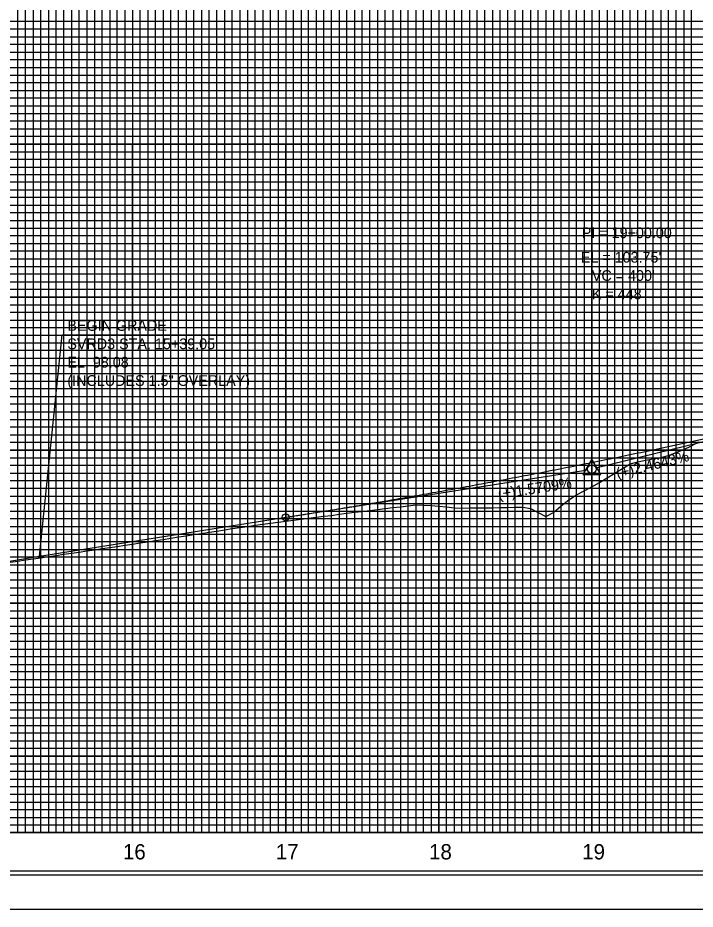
# Model space of a CAD drawing. Extents: x 2345490 to 2436403, y 465165 to 573888.
# Drawn here: x 2382292 to 2382734, y 500558 to 501140 of the extents above; entities that cross this region are included whole.
import ezdxf

# ---------------------------------------------------------------- set-up
doc = ezdxf.new("R2010")
doc.units = 0
for name, color, linetype in [('Exist Vertical Profile Horizontal Axis Label Major', 7, 'Continuous'), ('Old_Level_1', 7, 'Continuous'), ('Old_Level_18', 7, 'Continuous'), ('Old_Level_2', 7, 'Continuous'), ('Old_Level_41', 7, 'Continuous'), ('Old_Level_42', 7, 'Continuous'), ('Old_Level_43', 7, 'Continuous'), ('Old_Level_50', 7, 'Continuous'), ('Old_Level_51', 7, 'Continuous'), ('Old_Level_57', 7, 'Continuous'), ('Old_Level_63', 7, 'Continuous')]:
    doc.layers.add(name, color=color, linetype=linetype)

msp = doc.modelspace()

# ---------------------------------------------------------------- linework, layer by layer
at = {"layer": 'Old_Level_1'}
msp.add_lwpolyline([(2382286.7988, 500784.53371), (2382291.7988, 500785.26166), (2382296.7988, 500785.99237), (2382301.7988, 500786.72582), (2382306.7988, 500787.4614), (2382311.7988, 500788.18175), (2382316.7988, 500788.93271), (2382321.7988, 500789.68367), (2382326.7988, 500790.43463), (2382331.7988, 500791.18559), (2382336.7988, 500791.91779), (2382341.7988, 500792.64217), (2382346.7988, 500793.39156), (2382351.7988, 500794.14095), (2382356.7988, 500794.89034), (2382361.7988, 500795.63973), (2382366.7988, 500796.35105), (2382371.7988, 500797.12712), (2382376.7988, 500797.90319), (2382381.7988, 500798.67927), (2382386.7988, 500799.45534), (2382391.7988, 500800.23141), (2382396.7988, 500801.02584), (2382401.7988, 500801.8028), (2382406.7988, 500802.57976), (2382411.7988, 500803.35671), (2382416.7988, 500804.13367), (2382421.7988, 500804.91063), (2382426.7988, 500805.70098), (2382431.7988, 500806.44775), (2382436.7988, 500807.19218), (2382441.7988, 500807.9289), (2382446.7988, 500808.65766), (2382451.7988, 500809.36537), (2382456.7988, 500810.01704), (2382461.7988, 500810.71318), (2382466.7988, 500811.40027), (2382471.7988, 500812.07831), (2382476.7988, 500812.74727), (2382481.7988, 500813.35217), (2382486.7988, 500813.92844), (2382491.7988, 500814.54604), (2382496.7988, 500815.14977), (2382501.7988, 500815.87578), (2382506.7988, 500816.59153), (2382511.7988, 500817.18644), (2382516.7988, 500817.76146), (2382521.7988, 500818.3398), (2382526.7988, 500818.94403), (2382531.7988, 500819.55269), (2382536.7988, 500820.16259), (2382541.7988, 500820.76124), (2382546.7988, 500821.34863), (2382551.7988, 500821.92208), (2382556.7988, 500821.90141), (2382561.7988, 500821.52941), (2382566.7988, 500821.11082), (2382571.7988, 500820.64567), (2382576.7988, 500820.13395), (2382581.7988, 500819.90991), (2382586.7988, 500820.14813), (2382591.7988, 500820.14484), (2382596.7988, 500820.05054), (2382601.7988, 500820.01566), (2382606.7988, 500820.18657), (2382611.7988, 500820.31592), (2382616.7988, 500820.40371), (2382621.7988, 500820.44993), (2382626.7988, 500819.63463), (2382631.7988, 500817.08439), (2382636.7988, 500814.42424), (2382641.7988, 500817.00666), (2382646.7988, 500821.44876), (2382651.7988, 500825.21801), (2382656.7988, 500828.58451), (2382661.7988, 500831.10502), (2382666.7988, 500833.85905), (2382671.7988, 500836.69552), (2382676.7988, 500839.61461), (2382681.7988, 500842.61624), (2382686.7988, 500845.70031), (2382691.7988, 500848.86675), (2382696.7988, 500850.17491), (2382701.7988, 500851.12826), (2382706.7988, 500852.07957), (2382711.7988, 500853.0288), (2382716.7988, 500854.21109), (2382721.7988, 500856.22509), (2382726.7988, 500858.18432), (2382731.7988, 500860.50884), (2382736.7988, 500863.10854)], dxfattribs=at)
at = {"layer": 'Old_Level_18'}
msp.add_lwpolyline([(2383216.79875, 501632.775), (2381716.79875, 501632.775), (2381716.79875, 500582.775), (2383216.79875, 500582.775)], close=True, dxfattribs=at)
at = {"layer": 'Old_Level_2'}
for p, q in [((2382305.849, 500788.57525), (2382320.78925, 500933.0505)), ((2382320.78925, 500933.0505), (2382465.1055, 500933.0505)), ((2382866.799, 500894.56075), (2382669.46925, 500845.933)), ((2382466.799, 500813.858), (2382664.0825, 500844.84825)), ((2382305.849, 500788.57525), (2382466.799, 500813.858)), ((2382266.799, 500781.77575), (2382305.849, 500788.57525))]:
    msp.add_line(p, q, dxfattribs=at)
msp.add_lwpolyline([(2382660.99325, 500841.824), (2382672.73575, 500841.824), (2382666.86475, 500851.94975)], close=True, dxfattribs=at)
for centre, radius in [((2382666.799, 500845.275), 2.75), ((2382666.799, 500845.275), 2.75), ((2382466.799, 500813.858), 2.25)]:
    msp.add_circle(centre, radius, dxfattribs=at)
msp.add_spline([(2382466.799, 500813.858), (2382474.799, 500815.12175), (2382482.799, 500816.4), (2382490.799, 500817.6925), (2382498.799, 500818.99925), (2382506.799, 500820.32025), (2382514.799, 500821.6555), (2382522.799, 500823.005), (2382530.799, 500824.369), (2382538.799, 500825.74725), (2382546.799, 500827.1395), (2382554.799, 500828.5465), (2382562.799, 500829.9675), (2382570.799, 500831.40275), (2382578.799, 500832.8525), (2382586.799, 500834.3165), (2382594.799, 500835.79475), (2382602.799, 500837.28725), (2382610.799, 500838.794), (2382618.799, 500840.31525), (2382626.799, 500841.85075), (2382634.799, 500843.4005), (2382642.799, 500844.9645), (2382650.799, 500846.54275), (2382658.799, 500848.13525), (2382666.799, 500849.74225), (2382674.799, 500851.3635), (2382682.799, 500852.999), (2382690.799, 500854.64875), (2382698.799, 500856.31275), (2382706.799, 500857.99125), (2382714.799, 500859.684), (2382722.799, 500861.391), (2382730.799, 500863.11225), (2382738.799, 500864.84775), (2382746.799, 500866.5975), (2382754.799, 500868.36175), (2382762.799, 500870.14025), (2382770.799, 500871.933), (2382778.799, 500873.74), (2382786.799, 500875.56125), (2382794.799, 500877.397), (2382802.799, 500879.24675), (2382810.799, 500881.111), (2382818.799, 500882.9895), (2382826.799, 500884.8825), (2382834.799, 500886.7895), (2382842.799, 500888.711), (2382850.799, 500890.6465), (2382858.799, 500892.5965), (2382866.799, 500894.56075)], degree=3, dxfattribs=at)
at = {"layer": 'Old_Level_41'}
msp.add_line((2383216.79875, 500607.775), (2381716.79875, 500607.775), dxfattribs=at)
for points in [[(2382241.79875, 500607.775), (2382291.79875, 500607.775), (2382291.79875, 501632.775)], [(2382266.79875, 500607.775), (2382316.79875, 500607.775), (2382316.79875, 501632.775)], [(2382341.79875, 501632.775), (2382341.79875, 500607.775), (2382391.79875, 500607.775), (2382391.79875, 501632.775)], [(2382366.79875, 501632.775), (2382366.79875, 500607.775), (2382416.79875, 500607.775), (2382416.79875, 501632.775)], [(2382441.79875, 501632.775), (2382441.79875, 500607.775), (2382491.79875, 500607.775), (2382491.79875, 501632.775)], [(2382466.79875, 501632.775), (2382466.79875, 500607.775), (2382516.79875, 500607.775), (2382516.79875, 501632.775)], [(2382541.79875, 501632.775), (2382541.79875, 500607.775), (2382591.79875, 500607.775), (2382591.79875, 501632.775)], [(2382566.79875, 501632.775), (2382566.79875, 500607.775), (2382616.79875, 500607.775), (2382616.79875, 501632.775)], [(2382641.79875, 501632.775), (2382641.79875, 500607.775), (2382691.79875, 500607.775), (2382691.79875, 501632.775)], [(2382666.79875, 501632.775), (2382666.79875, 500607.775), (2382716.79875, 500607.775), (2382716.79875, 501632.775)], [(2383216.79875, 501132.775), (2381716.79875, 501132.775), (2381716.79875, 501082.775), (2383216.79875, 501082.775)], [(2383216.79875, 501032.775), (2381716.79875, 501032.775), (2381716.79875, 500982.775), (2383216.79875, 500982.775)], [(2383216.79875, 500957.775), (2381716.79875, 500957.775), (2381716.79875, 501007.775), (2383216.79875, 501007.775)], [(2383216.79875, 500932.775), (2381716.79875, 500932.775), (2381716.79875, 500882.775), (2383216.79875, 500882.775)], [(2383216.79875, 500857.775), (2381716.79875, 500857.775), (2381716.79875, 500907.775), (2383216.79875, 500907.775)], [(2383216.79875, 500832.775), (2381716.79875, 500832.775), (2381716.79875, 500782.775), (2383216.79875, 500782.775)], [(2383216.79875, 500732.775), (2381716.79875, 500732.775), (2381716.79875, 500682.775), (2383216.79875, 500682.775)], [(2383216.79875, 500657.775), (2381716.79875, 500657.775), (2381716.79875, 500707.775), (2383216.79875, 500707.775)], [(2383216.79875, 500632.775), (2381716.79875, 500632.775)]]:
    msp.add_lwpolyline(points, dxfattribs=at)
at = {"layer": 'Old_Level_42'}
for points in [[(2383216.79875, 501057.775), (2381716.79875, 501057.775), (2381716.79875, 501107.775), (2383216.79875, 501107.775)], [(2383216.79875, 500757.775), (2381716.79875, 500757.775), (2381716.79875, 500807.775), (2383216.79875, 500807.775)]]:
    msp.add_lwpolyline(points, dxfattribs=at)
at = {"layer": 'Old_Level_43'}
for points in [[(2382296.79875, 500607.775), (2382296.79875, 501632.775)], [(2382301.79875, 501632.775), (2382301.79875, 500607.775), (2382306.79875, 500607.775), (2382306.79875, 501632.775)], [(2382311.79875, 501632.775), (2382311.79875, 500607.775), (2382321.79875, 500607.775), (2382321.79875, 501632.775)], [(2382326.79875, 501632.775), (2382326.79875, 500607.775), (2382326.79875, 500607.775), (2382331.79875, 500607.775), (2382331.79875, 501632.775)], [(2382336.79875, 501632.775), (2382336.79875, 500607.775), (2382346.79875, 500607.775), (2382346.79875, 501632.775)], [(2382351.79875, 501632.775), (2382351.79875, 500607.775), (2382356.79875, 500607.775), (2382356.79875, 501632.775)], [(2382361.79875, 501632.775), (2382361.79875, 500607.775), (2382371.79875, 500607.775), (2382371.79875, 501632.775)], [(2382376.79875, 501632.775), (2382376.79875, 500607.775), (2382381.79875, 500607.775), (2382381.79875, 501632.775)], [(2382386.79875, 501632.775), (2382386.79875, 500607.775), (2382396.79875, 500607.775), (2382396.79875, 501632.775)], [(2382401.79875, 501632.775), (2382401.79875, 500607.775), (2382406.79875, 500607.775), (2382406.79875, 501632.775)], [(2382411.79875, 501632.775), (2382411.79875, 500607.775), (2382421.79875, 500607.775), (2382421.79875, 501632.775)], [(2382426.79875, 501632.775), (2382426.79875, 500607.775), (2382431.79875, 500607.775), (2382431.79875, 501632.775)], [(2382436.79875, 501632.775), (2382436.79875, 500607.775), (2382446.79875, 500607.775), (2382446.79875, 501632.775)], [(2382451.79875, 501632.775), (2382451.79875, 500607.775), (2382456.79875, 500607.775), (2382456.79875, 501632.775)], [(2382461.79875, 501632.775), (2382461.79875, 500607.775), (2382471.79875, 500607.775), (2382471.79875, 501632.775)], [(2382476.79875, 501632.775), (2382476.79875, 500607.775)], [(2382476.79875, 500607.775), (2382481.79875, 500607.775), (2382481.79875, 501632.175)], [(2382486.79875, 501632.175), (2382486.79875, 500607.775), (2382496.79875, 500607.775), (2382496.79875, 501632.775)], [(2382501.79875, 501632.775), (2382501.79875, 500607.775), (2382506.79875, 500607.775), (2382506.79875, 501632.775)], [(2382511.79875, 501632.775), (2382511.79875, 500607.775), (2382521.79875, 500607.775), (2382521.79875, 501632.775)], [(2382526.79875, 501632.775), (2382526.79875, 500607.775), (2382531.79875, 500607.775), (2382531.79875, 501632.775)], [(2382536.79875, 501632.775), (2382536.79875, 500607.775), (2382546.79875, 500607.775), (2382546.79875, 501632.775)], [(2382551.79875, 501632.775), (2382551.79875, 500607.775), (2382556.79875, 500607.775), (2382556.79875, 501632.775)], [(2382561.79875, 501632.775), (2382561.79875, 500607.775), (2382571.79875, 500607.775), (2382571.79875, 501632.775)], [(2382576.79875, 501632.775), (2382576.79875, 500607.775), (2382581.79875, 500607.775), (2382581.79875, 501632.775)], [(2382586.79875, 501632.775), (2382586.79875, 500607.775), (2382596.79875, 500607.775), (2382596.79875, 501632.775)], [(2382601.79875, 501632.775), (2382601.79875, 500607.775), (2382606.79875, 500607.775), (2382606.79875, 501632.775)], [(2382611.79875, 501632.775), (2382611.79875, 500607.775), (2382621.79875, 500607.775), (2382621.79875, 501632.775)], [(2382626.79875, 501632.775), (2382626.79875, 500607.775), (2382631.79875, 500607.775), (2382631.79875, 501632.775)], [(2382636.79875, 501632.775), (2382636.79875, 500607.775), (2382646.79875, 500607.775), (2382646.79875, 501632.775)], [(2382651.79875, 501632.775), (2382651.79875, 500607.775), (2382656.79875, 500607.775), (2382656.79875, 501632.775)], [(2382661.79875, 501632.775), (2382661.79875, 500607.775), (2382671.79875, 500607.775), (2382671.79875, 501632.775)], [(2382676.79875, 501632.775), (2382676.79875, 500607.775), (2382681.79875, 500607.775), (2382681.79875, 501632.775)], [(2382686.79875, 501632.775), (2382686.79875, 500607.775), (2382696.79875, 500607.775), (2382696.79875, 501632.775)], [(2382701.79875, 501632.775), (2382701.79875, 500607.775), (2382706.79875, 500607.775), (2382706.79875, 501632.775)], [(2382711.79875, 501632.775), (2382711.79875, 500607.775), (2382721.79875, 500607.775), (2382721.79875, 501632.775)], [(2382726.79875, 501632.775), (2382726.79875, 500607.775), (2382731.79875, 500607.775), (2382731.79875, 501632.775)], [(2383166.79875, 501137.775), (2381766.79875, 501137.775), (2381766.79875, 501127.775), (2383166.79875, 501127.775)], [(2383166.79875, 501122.775), (2381766.79875, 501122.775), (2381766.79875, 501117.775), (2383166.79875, 501117.775)], [(2383166.79875, 501112.775), (2381766.79875, 501112.775)], [(2381766.79875, 501102.775), (2383166.79875, 501102.775)], [(2383166.79875, 501097.775), (2381766.79875, 501097.775), (2381766.79875, 501092.775), (2383166.79875, 501092.775)], [(2383166.79875, 501087.775), (2381766.79875, 501087.775), (2381766.79875, 501077.775), (2383166.79875, 501077.775)], [(2383166.79875, 501072.775), (2381766.79875, 501072.775), (2381766.79875, 501067.775), (2383166.79875, 501067.775)], [(2383166.79875, 501062.775), (2381766.79875, 501062.775), (2381766.79875, 501052.775), (2383166.79875, 501052.775)], [(2383166.79875, 501047.775), (2381766.79875, 501047.775), (2381766.79875, 501042.775), (2383166.79875, 501042.775)], [(2383166.79875, 501037.775), (2381766.79875, 501037.775), (2381766.79875, 501027.775), (2383166.79875, 501027.775)], [(2383166.79875, 501022.775), (2381766.79875, 501022.775), (2381766.79875, 501017.775), (2383166.79875, 501017.775)], [(2383166.79875, 501012.775), (2381766.79875, 501012.775), (2381766.79875, 501002.775), (2383166.79875, 501002.775)], [(2383166.79875, 500997.775), (2381766.79875, 500997.775), (2381766.79875, 500992.775), (2383166.79875, 500992.775)], [(2383166.79875, 500987.775), (2381766.79875, 500987.775), (2381766.79875, 500977.775), (2383166.79875, 500977.775)], [(2383166.79875, 500972.775), (2381766.79875, 500972.775), (2381766.79875, 500967.775), (2383166.79875, 500967.775)], [(2383166.79875, 500962.775), (2381766.79875, 500962.775), (2381766.79875, 500952.775), (2383166.79875, 500952.775)], [(2383166.79875, 500947.775), (2381766.79875, 500947.775), (2381766.79875, 500942.775), (2383166.79875, 500942.775)], [(2383166.79875, 500937.775), (2381766.79875, 500937.775), (2381766.79875, 500927.775), (2383166.79875, 500927.775)], [(2383166.79875, 500922.775), (2381766.79875, 500922.775), (2381766.79875, 500917.775), (2383166.79875, 500917.775)], [(2383166.79875, 500912.775), (2381766.79875, 500912.775), (2381766.79875, 500902.775), (2383166.79875, 500902.775)], [(2383166.79875, 500897.775), (2381766.79875, 500897.775), (2381766.79875, 500892.775), (2383166.79875, 500892.775)], [(2383166.79875, 500887.775), (2381766.79875, 500887.775), (2381766.79875, 500877.775), (2383166.79875, 500877.775)], [(2383166.79875, 500872.775), (2381766.79875, 500872.775), (2381766.79875, 500867.775), (2383166.79875, 500867.775)], [(2383166.79875, 500862.775), (2381766.79875, 500862.775), (2381766.79875, 500852.775), (2383166.79875, 500852.775)], [(2383166.79875, 500847.775), (2381766.79875, 500847.775), (2381766.79875, 500842.775), (2383166.79875, 500842.775)], [(2383166.79875, 500837.775), (2381766.79875, 500837.775), (2381766.79875, 500827.775), (2383166.79875, 500827.775)], [(2383166.79875, 500822.775), (2381766.79875, 500822.775), (2381766.79875, 500817.775), (2383166.79875, 500817.775)], [(2383166.79875, 500812.775), (2381766.79875, 500812.775)], [(2381766.79875, 500802.775), (2383166.79875, 500802.775)], [(2383166.79875, 500797.775), (2381766.79875, 500797.775), (2381766.79875, 500792.775), (2383166.79875, 500792.775)], [(2383166.79875, 500787.775), (2381766.79875, 500787.775)], [(2381766.79875, 500777.775), (2383166.79875, 500777.775)], [(2383166.79875, 500772.775), (2381766.79875, 500772.775), (2381766.79875, 500767.775), (2383166.79875, 500767.775)], [(2383166.79875, 500762.775), (2381766.79875, 500762.775), (2381766.79875, 500752.775), (2383166.79875, 500752.775)], [(2383166.79875, 500747.775), (2381766.79875, 500747.775), (2381766.79875, 500742.775), (2383166.79875, 500742.775)], [(2383166.79875, 500737.775), (2381766.79875, 500737.775), (2381766.79875, 500727.775), (2383166.79875, 500727.775)], [(2383166.79875, 500722.775), (2381766.79875, 500722.775), (2381766.79875, 500717.775), (2383166.79875, 500717.775)], [(2383166.79875, 500712.775), (2381766.79875, 500712.775), (2381766.79875, 500702.775), (2383166.79875, 500702.775)], [(2383166.79875, 500697.775), (2381766.79875, 500697.775), (2381766.79875, 500692.775), (2383166.79875, 500692.775)], [(2383166.79875, 500687.775), (2381766.79875, 500687.775), (2381766.79875, 500677.775), (2383166.79875, 500677.775)], [(2383166.79875, 500672.775), (2381766.79875, 500672.775), (2381766.79875, 500667.775), (2383166.79875, 500667.775)], [(2383166.79875, 500662.775), (2381766.79875, 500662.775), (2381766.79875, 500652.775), (2383166.79875, 500652.775)], [(2383166.79875, 500647.775), (2381766.79875, 500647.775), (2381766.79875, 500642.775), (2383166.79875, 500642.775)], [(2383166.79875, 500637.775), (2381766.79875, 500637.775), (2381766.79875, 500627.775), (2383166.79875, 500627.775)], [(2383166.79875, 500622.775), (2381766.79875, 500622.775), (2381766.79875, 500617.775), (2383166.79875, 500617.775)], [(2383166.79875, 500612.775), (2381766.79875, 500612.775)]]:
    msp.add_lwpolyline(points, dxfattribs=at)
at = {"layer": 'Old_Level_50'}
msp.add_lwpolyline([(2383229.29875, 501635.325), (2381562.79875, 501635.325), (2381562.79875, 500580.225), (2383229.29875, 500580.225)], close=True, dxfattribs=at)
at = {"layer": 'Old_Level_51'}
msp.add_lwpolyline([(2383233.79875, 501657.775), (2381549.79875, 501657.775), (2381549.79875, 500557.775), (2383233.79875, 500557.775)], close=True, dxfattribs=at)
at = {"layer": 'Old_Level_57'}
for p, q in [((2381716.79925, 501057.77525), (2385066.79875, 501057.77525)), ((2382366.79875, 500607.77525), (2382366.79875, 501057.77525)), ((2382366.79875, 500607.87525), (2382366.79875, 501057.77525)), ((2382466.79875, 500607.77525), (2382466.79875, 501057.77525)), ((2382466.79875, 500607.87525), (2382466.79875, 501057.77525)), ((2382566.79875, 500607.77525), (2382566.79875, 501057.77525)), ((2382566.79875, 500607.87525), (2382566.79875, 501057.77525)), ((2382666.79875, 500607.77525), (2382666.79875, 501057.77525)), ((2382666.79875, 500607.87525), (2382666.79875, 501057.77525)), ((2381716.79925, 501007.77525), (2385066.79875, 501007.77525)), ((2381716.79925, 500957.77525), (2385066.79875, 500957.77525)), ((2381716.79925, 500907.77525), (2385066.79875, 500907.77525)), ((2381716.79925, 500857.77525), (2385066.79875, 500857.77525)), ((2381716.79925, 500807.77525), (2385066.79875, 500807.77525)), ((2381716.79925, 500757.77525), (2385066.79875, 500757.77525)), ((2381716.79925, 500707.77525), (2385066.79875, 500707.77525)), ((2381716.799, 500657.77525), (2385066.79875, 500657.77525)), ((2381716.79925, 500607.77525), (2385066.79875, 500607.77525))]:
    msp.add_line(p, q, dxfattribs=at)
at = {"layer": 'Old_Level_63'}
msp.add_line((2381766.79875, 500607.775), (2384797.7405, 500607.775), dxfattribs=at)

# ---------------------------------------------------------------- texts
at = {"layer": 'Exist Vertical Profile Horizontal Axis Label Major'}
for s, p in [('16', (2382360.48062, 500590.275)), ('17', (2382460.33819, 500590.275)), ('18', (2382560.46395, 500590.275)), ('19', (2382660.50638, 500590.275))]:
    msp.add_text(s, height=10, dxfattribs=at).set_placement(p)
at = {"layer": 'Old_Level_2'}
for s, height, p in [('PI = 19+00.00', 7.0000005, (2382660.19375, 500996.302)), ("EL = 103.75'", 7.0000005, (2382659.57625, 500980.3155)), ("VC = 400'", 7.000001, (2382666.79925, 500968.391)), ('K = 448', 7.000001, (2382666.799, 500956.3745)), ('BEGIN GRADE', 7.0000005, (2382324.15075, 500935.73775)), ('SVRD3 STA. 15+39.05', 7.0000005, (2382324.15075, 500923.73775)), ('EL. 98.08', 7.000001, (2382324.15075, 500911.73775)), ('(INCLUDES 1.5" OVERLAY)', 7.0000005, (2382324.15075, 500899.73775))]:
    msp.add_text(s, height=height, dxfattribs=at).set_placement(p)
for s, rotation, p in [('(+)2.4643%', 13.84349167, (2382683.632, 500839.12425)), ('(+)1.5709%', 8.92738056, (2382605.97025, 500825.59725))]:
    msp.add_text(s, height=7.000001, rotation=rotation, dxfattribs=at).set_placement(p)

doc.saveas('drawing.dxf')
